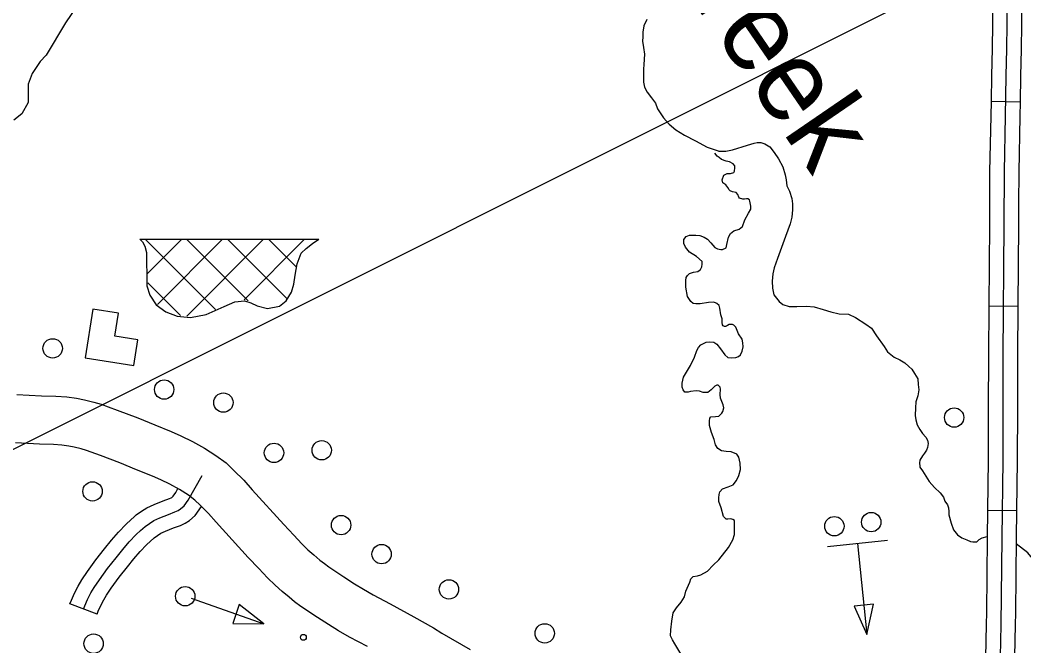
# Model space of a CAD drawing. Extents: x 1382482 to 1385815, y 1168351 to 1170484.
# Drawn here: x 1383658.5 to 1383865.9, y 1168868.8 to 1168998.2 of the extents above; entities that cross this region are included whole.
import ezdxf

# ---------------------------------------------------------------- set-up
doc = ezdxf.new("R2010")
doc.units = 0
for name, color, linetype in [('10', 7, 'Continuous'), ('35', 7, 'Continuous'), ('45', 7, 'Continuous'), ('57', 7, 'Continuous'), ('Default', 7, 'Continuous'), ('R_Dimension', 7, 'Continuous')]:
    doc.layers.add(name, color=color, linetype=linetype)

msp = doc.modelspace()

# ---------------------------------------------------------------- linework, layer by layer
at = {"layer": '10'}
for points in [[(1383657.78, 1168920.79), (1383662.89, 1168920.53), (1383665.86, 1168920.44), (1383668.1, 1168920.29), (1383670.1, 1168920.02), (1383671.79, 1168919.7), (1383673.68, 1168919.21), (1383675.22, 1168918.79), (1383676.66, 1168918.26), (1383678.56, 1168917.54), (1383682.77, 1168915.98), (1383686.28, 1168914.5), (1383689.7, 1168913.14), (1383691.7, 1168912.26), (1383694.09, 1168911.11), (1383696.58, 1168909.69), (1383698.89, 1168908.22), (1383701.03, 1168906.66), (1383702.65, 1168905.09), (1383704.69, 1168903.06), (1383706.41, 1168901.11), (1383712.94, 1168893.9), (1383715.02, 1168891.71), (1383716.7, 1168889.93), (1383717.93, 1168888.73), (1383719.16, 1168887.66), (1383720.43, 1168886.59), (1383721.33, 1168885.84), (1383722.24, 1168885.17), (1383725.36, 1168883.11), (1383727.54, 1168881.7), (1383729.41, 1168880.56), (1383731.41, 1168879.38), (1383734.94, 1168877.53), (1383739.84, 1168874.86), (1383743.87, 1168872.55), (1383745.59, 1168871.51), (1383751.44, 1168868.08)], [(1383730.22, 1168868.7), (1383726.54, 1168870.64), (1383724.25, 1168871.99), (1383722.22, 1168873.24), (1383719.9, 1168874.73), (1383716.49, 1168876.98), (1383715.17, 1168877.96), (1383714.03, 1168878.9), (1383712.65, 1168880.06), (1383711.14, 1168881.38), (1383709.56, 1168882.92), (1383707.77, 1168884.82), (1383705.61, 1168887.09), (1383698.97, 1168894.44), (1383697.4, 1168896.2), (1383695.65, 1168897.95), (1383694.58, 1168898.98), (1383693.25, 1168899.96), (1383691.41, 1168901.13), (1383689.44, 1168902.25), (1383687.53, 1168903.17), (1383685.85, 1168903.91), (1383682.49, 1168905.24), (1383679.08, 1168906.69), (1383675.05, 1168908.18), (1383673.19, 1168908.89), (1383672.19, 1168909.25), (1383671.09, 1168909.55), (1383669.61, 1168909.94), (1383668.51, 1168910.14), (1383667.09, 1168910.34), (1383665.38, 1168910.45), (1383662.48, 1168910.54), (1383657.53, 1168910.79)]]:
    msp.add_lwpolyline(points, dxfattribs=at)
at = {"layer": '35'}
for points in [[(1383672.95, 1169005.17), (1383667.83, 1168997.58), (1383663.85, 1168990.94), (1383662.63, 1168989.61), (1383660.97, 1168987.15), (1383660.15, 1168984.94), (1383660.14, 1168981.1), (1383658.8, 1168978.76), (1383657.17, 1168977.47)], [(1383787.97, 1168998.28), (1383787.36, 1168996.94), (1383787.1, 1168995.68), (1383787.14, 1168994.69), (1383787.06, 1168993.77), (1383787.29, 1168992.47), (1383787.48, 1168991.14), (1383787.44, 1168990.07), (1383787.33, 1168988.93), (1383787.29, 1168988.05), (1383787.29, 1168987.02), (1383787.29, 1168986.18), (1383787.29, 1168985.31), (1383787.48, 1168984.32), (1383788.01, 1168983.25), (1383788.93, 1168982.07), (1383789.77, 1168980.96), (1383790.18, 1168979.82), (1383791.37, 1168977.99), (1383792.59, 1168976.62), (1383793.92, 1168975.51), (1383795.71, 1168974.41), (1383798, 1168973.22), (1383800.44, 1168971.89), (1383802.68, 1168971.13), (1383802.86, 1168971.1)], [(1383802.86, 1168971.1), (1383804.3, 1168971.04), (1383805.69, 1168971.32), (1383808.73, 1168972.31), (1383810.15, 1168972.74), (1383810.78, 1168972.86), (1383811.49, 1168972.86), (1383812.36, 1168972.62), (1383813.34, 1168971.95), (1383814.29, 1168970.81), (1383815.16, 1168969.5), (1383816.07, 1168967.84), (1383816.54, 1168966.18), (1383816.74, 1168965.12), (1383816.9, 1168963.93), (1383817.41, 1168962.83), (1383817.92, 1168961.29), (1383818.08, 1168960.18), (1383818.04, 1168958.92), (1383817.92, 1168957.42), (1383817.57, 1168956.06), (1383816.62, 1168953.45), (1383814.96, 1168948.91), (1383814.25, 1168946.97), (1383814.02, 1168945.75), (1383813.82, 1168944.21), (1383813.9, 1168942.75), (1383814.21, 1168941.36), (1383815.28, 1168939.98), (1383816.07, 1168939.39), (1383817.37, 1168939), (1383818.95, 1168939), (1383820.96, 1168939.07), (1383822.5, 1168938.88), (1383824.38, 1168938.35), (1383826, 1168937.87), (1383827.66, 1168937.48), (1383829.63, 1168937.36), (1383831.09, 1168936.73), (1383833.23, 1168935.35), (1383834.37, 1168934.48), (1383835.44, 1168932.9), (1383836.98, 1168930.73), (1383837.65, 1168929.58), (1383839.03, 1168928.51), (1383840.21, 1168927.96), (1383841.28, 1168927.33), (1383842.11, 1168926.58), (1383842.74, 1168926.03), (1383843.29, 1168925.12), (1383843.96, 1168924.01), (1383844.04, 1168922.87), (1383844.12, 1168921.76), (1383843.96, 1168920.5), (1383843.53, 1168919.27), (1383843.49, 1168918.01), (1383843.41, 1168916.47), (1383843.55, 1168915.55), (1383843.79, 1168914.56), (1383844.34, 1168913.58), (1383844.89, 1168912.71), (1383845.61, 1168912), (1383845.96, 1168911.37), (1383846.08, 1168910.65), (1383845.98, 1168910.28), (1383845.94, 1168909.81), (1383845.72, 1168909.27), (1383845.33, 1168908.64), (1383844.93, 1168908.13), (1383844.38, 1168907.22), (1383844.3, 1168906.7), (1383844.34, 1168905.92), (1383844.34, 1168905.76), (1383844.89, 1168905.01), (1383846.32, 1168902.79), (1383847.38, 1168901.57), (1383848.53, 1168900.5), (1383849.24, 1168899.6), (1383849.55, 1168898.77), (1383850.07, 1168897.98), (1383850.26, 1168897.38), (1383850.38, 1168896.63), (1383850.34, 1168895.92), (1383850.82, 1168894.19), (1383851.33, 1168892.85), (1383852.16, 1168891.78), (1383853.07, 1168891.19), (1383854.05, 1168890.75), (1383854.84, 1168890.44), (1383855.32, 1168890.36), (1383855.79, 1168890.36), (1383856.11, 1168890.36), (1383856.62, 1168890.83), (1383857.25, 1168891.19), (1383858.29, 1168891.48)], [(1383803.69, 1168964.53), (1383803.5, 1168965.18), (1383803.85, 1168966.09), (1383804.53, 1168966.44), (1383805.22, 1168966.48), (1383805.94, 1168966.63), (1383806.1, 1168966.97), (1383806.17, 1168967.65), (1383806.17, 1168968.03), (1383805.79, 1168968.45), (1383805.03, 1168968.87), (1383804.34, 1168968.98), (1383803.4, 1168969.36), (1383802.87, 1168969.78), (1383802.47, 1168970.05), (1383802, 1168970.67)], [(1383797.79, 1168928.48), (1383798.32, 1168929.88), (1383798.63, 1168930.53), (1383799.12, 1168931.06), (1383800.23, 1168931.6), (1383800.99, 1168931.67), (1383801.79, 1168931.64), (1383802.44, 1168931.18), (1383803.16, 1168930.23), (1383804.04, 1168929.01), (1383804.72, 1168928.47), (1383805.49, 1168928.36), (1383806.36, 1168928.47), (1383806.93, 1168928.62), (1383807.31, 1168929.01), (1383807.62, 1168929.77), (1383807.85, 1168930.64), (1383807.77, 1168931.48), (1383807.62, 1168932.25), (1383806.93, 1168933.35), (1383806.32, 1168934.69), (1383805.94, 1168935.1), (1383805.64, 1168935.26), (1383805.3, 1168935.26), (1383804.95, 1168935.26), (1383804.61, 1168935.03), (1383804.42, 1168934.88), (1383804.19, 1168934.84), (1383804, 1168934.84), (1383803.73, 1168934.99), (1383803.58, 1168935.22), (1383803.5, 1168935.64), (1383803.5, 1168936.4), (1383803.24, 1168937.24), (1383803.01, 1168938.66), (1383802.89, 1168939.15), (1383802.4, 1168939.61), (1383802.17, 1168939.76), (1383801.75, 1168939.84), (1383800.68, 1168939.8), (1383798.97, 1168939.53), (1383798.09, 1168939.5), (1383797.56, 1168939.57), (1383797.06, 1168940.03), (1383796.38, 1168941.02), (1383796.03, 1168942.96), (1383796, 1168944.34), (1383796.11, 1168944.99), (1383796.38, 1168945.37), (1383796.8, 1168945.79), (1383797.6, 1168946.09), (1383798.47, 1168946.21), (1383799.05, 1168946.62), (1383799.31, 1168947.2), (1383799.39, 1168947.69), (1383799.39, 1168948.26), (1383798.24, 1168949.29), (1383796.76, 1168950.17), (1383795.92, 1168951.24), (1383795.58, 1168952), (1383795.62, 1168952.84), (1383796.11, 1168953.41), (1383796.76, 1168953.71), (1383797.33, 1168953.71), (1383798.09, 1168953.71), (1383798.89, 1168953.64), (1383799.77, 1168953.3), (1383800.49, 1168952.88), (1383801.18, 1168952.15), (1383801.98, 1168951.16), (1383802.59, 1168950.86), (1383803.24, 1168950.74), (1383803.62, 1168950.78), (1383804.34, 1168951.12), (1383804.49, 1168951.81), (1383804.84, 1168953.33), (1383805.22, 1168954.06), (1383805.9, 1168954.59), (1383807.01, 1168954.93), (1383807.7, 1168955.54), (1383808.23, 1168956.87), (1383808.99, 1168958.28), (1383809.45, 1168959.08), (1383809.45, 1168959.73), (1383809.22, 1168960.72), (1383809.14, 1168960.99), (1383808.84, 1168961.22), (1383808.72, 1168961.22), (1383808.53, 1168961.22), (1383808.11, 1168961.18), (1383807.81, 1168961.18), (1383807.09, 1168961.37), (1383806.97, 1168961.56), (1383806.78, 1168962.09), (1383806.4, 1168962.55), (1383805.68, 1168962.66), (1383805.18, 1168962.85), (1383804.95, 1168963.08), (1383804.72, 1168963.54), (1383804.27, 1168964.11), (1383803.69, 1168964.53)], [(1383794.97, 1168867.21), (1383793.71, 1168869.3), (1383793.25, 1168870.07), (1383792.87, 1168870.96), (1383792.91, 1168872.14), (1383793.1, 1168873.97), (1383793.37, 1168875.65), (1383794.09, 1168876.72), (1383795.08, 1168877.9), (1383795.77, 1168878.97), (1383796.03, 1168880.19), (1383796.87, 1168882.05), (1383797.06, 1168882.74), (1383797.56, 1168883.16), (1383798.44, 1168883.31), (1383799.12, 1168883.54), (1383800.46, 1168884.27), (1383801.64, 1168885.52), (1383802.8, 1168886.65), (1383804.86, 1168889.16), (1383805.73, 1168890.76), (1383806.08, 1168891.87), (1383806.08, 1168893.24), (1383806.08, 1168894.23), (1383806.04, 1168894.58), (1383806.04, 1168894.73), (1383805.73, 1168895), (1383805.28, 1168895.07), (1383804.67, 1168895.03), (1383804.36, 1168895.03), (1383803.79, 1168895.61), (1383803.29, 1168897.36), (1383802.84, 1168898.69), (1383802.84, 1168899.46), (1383802.91, 1168900.14), (1383803.03, 1168900.71), (1383803.6, 1168901.29), (1383804.78, 1168901.74), (1383805.81, 1168902.16), (1383806.46, 1168903.04), (1383806.99, 1168904.06), (1383807.3, 1168905.28), (1383807.26, 1168906.61), (1383806.95, 1168907.87), (1383806.57, 1168908.44), (1383805.39, 1168908.94), (1383804.32, 1168909.02), (1383803.41, 1168909.17), (1383802.61, 1168909.63), (1383802.15, 1168910.39), (1383801.85, 1168911.49), (1383801.35, 1168912.94), (1383800.89, 1168914.41), (1383800.92, 1168915.36), (1383800.95, 1168915.93), (1383801.18, 1168916.2), (1383802.17, 1168916.28), (1383802.86, 1168916.35), (1383803.43, 1168916.96), (1383803.69, 1168917.31), (1383803.85, 1168918.03), (1383803.73, 1168918.64), (1383803.16, 1168920.01), (1383803.08, 1168920.78), (1383803.16, 1168921.92), (1383803.12, 1168922.3), (1383802.7, 1168922.72), (1383802.4, 1168922.72), (1383801.98, 1168922.53), (1383801.26, 1168921.73), (1383800.53, 1168921.23), (1383799.62, 1168921.23), (1383798.82, 1168921.46), (1383798.17, 1168921.54), (1383796.99, 1168921.39), (1383796.49, 1168921.31), (1383795.84, 1168921.31), (1383795.46, 1168921.73), (1383795.23, 1168922.34), (1383795.23, 1168923.14), (1383795.54, 1168924.4), (1383796.15, 1168925.43), (1383796.95, 1168926.8), (1383797.79, 1168928.48)], [(1383899.24, 1168857.33), (1383895.5, 1168858.73), (1383891.83, 1168859.72), (1383887.56, 1168861.11), (1383885.75, 1168862.05), (1383884.41, 1168862.83), (1383882.43, 1168865.38), (1383881.69, 1168867.23), (1383881.65, 1168868.18), (1383881.09, 1168869.52), (1383880.23, 1168870.73), (1383878.29, 1168872.67), (1383876.17, 1168874.7), (1383873.32, 1168877.9), (1383871.77, 1168880.31), (1383871.17, 1168882.13), (1383870, 1168883.94), (1383869.01, 1168885.28), (1383866.68, 1168888.08), (1383864.27, 1168889.95)]]:
    msp.add_lwpolyline(points, dxfattribs=at)
at = {"layer": '45'}
for p, q in [((1383859.07, 1168981.37), (1383865.07, 1168981.28)), ((1383858.61, 1168939.11), (1383864.61, 1168939.07)), ((1383858.36, 1168896.89), (1383864.36, 1168896.81)), ((1383674.41, 1168875.42), (1383668.78, 1168877.52))]:
    msp.add_line(p, q, dxfattribs=at)
for points in [[(1383863.13, 1169023.53), (1383862.8, 1169021.88), (1383862.43, 1169002.5), (1383862.27, 1168992.22), (1383862.15, 1168986.62), (1383862.02, 1168978.27), (1383861.78, 1168966.84), (1383861.74, 1168955.92), (1383861.53, 1168928.91), (1383861.49, 1168907.19), (1383861.29, 1168891.15), (1383861.08, 1168873.23), (1383860.8, 1168859.97), (1383860.88, 1168856.58), (1383860.99, 1168854.9)], [(1383859.43, 1169002.49), (1383859.27, 1168992.28), (1383859.15, 1168986.67), (1383859.07, 1168981.37)], [(1383865.43, 1169002.4), (1383865.27, 1168992.16), (1383865.15, 1168986.56), (1383865.07, 1168981.28)], [(1383859.07, 1168981.37), (1383859.02, 1168978.33), (1383858.78, 1168966.88), (1383858.75, 1168960.22)], [(1383865.07, 1168981.28), (1383865.02, 1168978.22), (1383864.78, 1168966.8), (1383864.75, 1168960.2)], [(1383858.75, 1168960.22), (1383858.74, 1168955.94), (1383858.61, 1168939.11)], [(1383864.75, 1168960.2), (1383864.74, 1168955.9), (1383864.61, 1168939.07)], [(1383858.61, 1168939.11), (1383858.53, 1168928.93), (1383858.51, 1168917.98)], [(1383864.61, 1168939.07), (1383864.53, 1168928.9), (1383864.51, 1168917.97)], [(1383858.51, 1168917.98), (1383858.49, 1168907.21), (1383858.36, 1168896.89)], [(1383864.51, 1168917.97), (1383864.49, 1168907.17), (1383864.36, 1168896.81)], [(1383671.59, 1168876.47), (1383671.84, 1168877.13), (1383672.43, 1168878.47), (1383673.1, 1168879.78), (1383673.75, 1168880.91), (1383674.85, 1168882.51), (1383676.54, 1168884.84), (1383678.29, 1168887.04), (1383679.67, 1168888.79), (1383681.04, 1168890.35), (1383682.47, 1168891.86), (1383683.37, 1168892.69), (1383684.32, 1168893.55), (1383685.22, 1168894.17), (1383686.12, 1168894.75), (1383687.35, 1168895.34), (1383689.13, 1168896.02), (1383690.46, 1168896.52), (1383691.15, 1168896.82), (1383691.64, 1168897.15), (1383692.35, 1168897.78), (1383693.17, 1168898.96), (1383696.07, 1168904.09)], [(1383682.06, 1168895.54), (1383682.45, 1168895.9), (1383683.55, 1168896.67), (1383684.66, 1168897.37), (1383686.16, 1168898.09), (1383688.06, 1168898.83), (1383689.33, 1168899.3), (1383689.71, 1168899.47), (1383689.81, 1168899.54), (1383690.08, 1168899.78), (1383690.62, 1168900.56), (1383691.07, 1168901.35)], [(1383686.07, 1168891.08), (1383686.2, 1168891.19), (1383686.89, 1168891.68), (1383687.57, 1168892.12), (1383688.54, 1168892.58), (1383690.19, 1168893.22), (1383691.59, 1168893.74), (1383692.59, 1168894.18), (1383693.47, 1168894.76), (1383694.61, 1168895.78), (1383695.93, 1168897.68)], [(1383858.36, 1168896.89), (1383858.29, 1168891.19), (1383858.11, 1168875.77)], [(1383864.36, 1168896.81), (1383864.29, 1168891.12), (1383864.11, 1168875.7)], [(1383668.78, 1168877.52), (1383669.06, 1168878.27), (1383669.72, 1168879.76), (1383670.46, 1168881.21), (1383671.21, 1168882.51), (1383672.4, 1168884.24), (1383674.15, 1168886.66), (1383675.94, 1168888.9), (1383677.36, 1168890.71), (1383678.82, 1168892.38), (1383680.36, 1168894), (1383681.35, 1168894.91), (1383682.06, 1168895.54)], [(1383674.41, 1168875.42), (1383674.62, 1168876), (1383675.15, 1168877.18), (1383675.74, 1168878.36), (1383676.29, 1168879.31), (1383677.31, 1168880.78), (1383678.93, 1168883.03), (1383680.65, 1168885.18), (1383681.98, 1168886.87), (1383683.25, 1168888.33), (1383684.57, 1168889.72), (1383685.39, 1168890.47), (1383686.07, 1168891.08)], [(1383858.11, 1168875.77), (1383858.08, 1168873.28), (1383857.79, 1168859.58)], [(1383864.11, 1168875.7), (1383864.08, 1168873.18), (1383863.8, 1168860.08)]]:
    msp.add_lwpolyline(points, dxfattribs=at)
at = {"layer": '57'}
for p, q in [((1383683.24, 1168952.92), (1383720.2, 1168952.92)), ((1383698.85, 1168938.38), (1383684.47, 1168952.77)), ((1383684.77, 1168945.82), (1383691.72, 1168952.78)), ((1383686.83, 1168939.4), (1383700.16, 1168952.73)), ((1383705.58, 1168940.14), (1383692.91, 1168952.81)), ((1383692.92, 1168937.01), (1383708.71, 1168952.8)), ((1383713.55, 1168940.65), (1383701.48, 1168952.72)), ((1383704.76, 1168940.36), (1383717.12, 1168952.73)), ((1383715.42, 1168947.27), (1383709.95, 1168952.74)), ((1383691.63, 1168937.12), (1383684.89, 1168943.86))]:
    msp.add_line(p, q, dxfattribs=at)
msp.add_lwpolyline([(1383683.24, 1168952.92), (1383683.77, 1168952.34), (1383684.27, 1168951.46), (1383684.6, 1168950.13), (1383684.6, 1168948.15), (1383684.65, 1168945.55), (1383684.65, 1168943.23), (1383685.31, 1168941.3), (1383686.58, 1168939.31), (1383688.57, 1168937.87), (1383690.89, 1168936.99), (1383693.71, 1168936.71), (1383696.91, 1168937.32), (1383700.61, 1168938.98), (1383702.87, 1168939.97), (1383704.81, 1168940.14), (1383706.13, 1168939.75), (1383707.46, 1168939.09), (1383709.61, 1168938.59), (1383712.1, 1168939.03), (1383713.42, 1168940.14), (1383714.53, 1168941.96), (1383715.02, 1168943.56), (1383715.3, 1168945.44), (1383715.74, 1168947.81), (1383716.51, 1168949.97), (1383717.56, 1168950.96), (1383718.89, 1168952.01), (1383720.2, 1168952.92)], dxfattribs=at)
at = {"layer": 'Default'}
msp.add_line((1383693.8, 1168878.69), (1383708.85, 1168873.42), dxfattribs=at)
for points in [[(1383671.92, 1168928.39), (1383681.95, 1168926.82), (1383682.78, 1168932.11), (1383678.04, 1168932.86), (1383678.78, 1168937.6), (1383673.49, 1168938.43)], [(1383703.74, 1168877.37), (1383702.4, 1168873.51), (1383708.85, 1168873.42)], [(1383834.82, 1168877.49), (1383830.76, 1168877.07), (1383833.41, 1168871.19)]]:
    msp.add_lwpolyline(points, close=True, dxfattribs=at)
for points in [[(1383837.7, 1168890.63), (1383825.27, 1168889.35)], [(1383831.49, 1168889.99), (1383833.41, 1168871.19)]]:
    msp.add_lwpolyline(points, dxfattribs=at)
for centre, radius in [((1383665.2, 1168930.33), 2), ((1383688.24, 1168921.82), 2), ((1383700.47, 1168919.12), 2), ((1383851.45, 1168916.03), 2), ((1383710.93, 1168908.73), 2), ((1383720.79, 1168909.27), 2), ((1383673.44, 1168900.78), 2), ((1383834.32, 1168894.42), 2), ((1383724.79, 1168893.81), 2), ((1383826.7, 1168893.58), 2), ((1383733.16, 1168887.81), 2), ((1383747.07, 1168880.53), 2), ((1383692.58, 1168879.11), 2), ((1383766.86, 1168871.44), 2), ((1383673.66, 1168869.31), 2), ((1383717, 1168870.62), 0.6)]:
    msp.add_circle(centre, radius, dxfattribs=at)
at = {"layer": 'R_Dimension'}
msp.add_line((1383356.44, 1168759.04), (1384183.61, 1169173.06), dxfattribs=at)

# ---------------------------------------------------------------- texts
at = {"layer": '35'}
msp.add_text('Creek', height=16.896, rotation=304.411, dxfattribs=at).set_placement((1383788.15, 1169015.54))

doc.saveas('drawing.dxf')
